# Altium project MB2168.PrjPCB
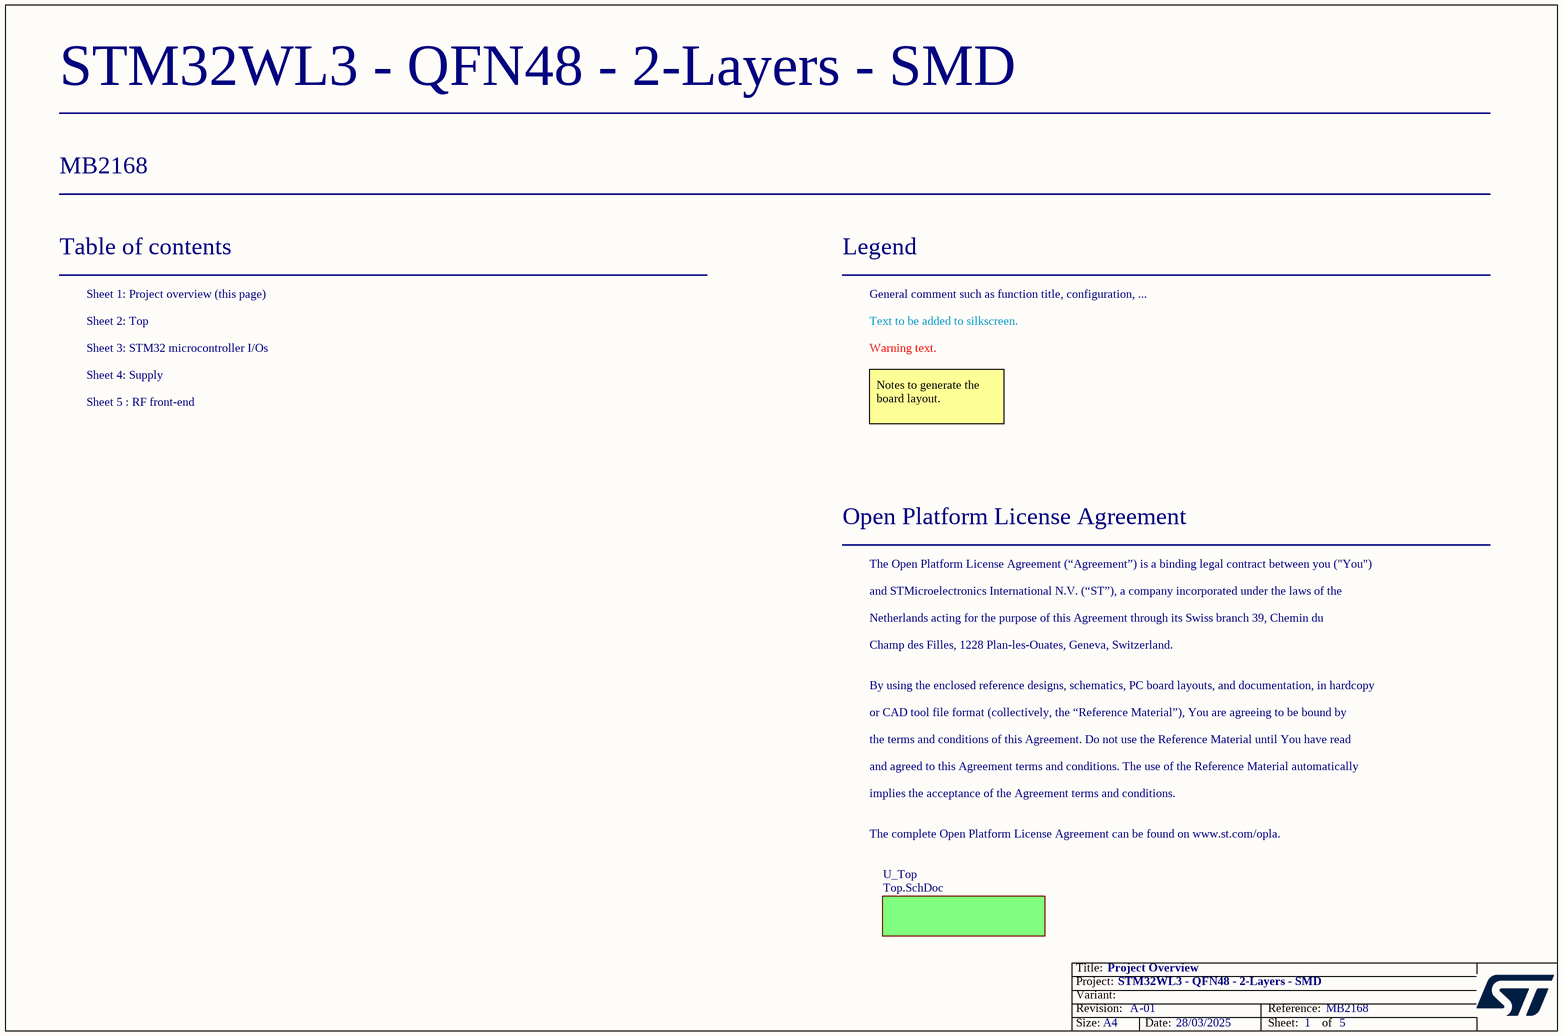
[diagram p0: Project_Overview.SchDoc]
Board_Reference: MB2168; Board_PCB_Revision: A; Board_Name: STM32WL3 - QFN48 - 2-Layers - SMD; Board_Document_Date: 28/03/2025; Board_Assembly_Revision: 01
5 sheets, 80 parts. Net scope: flat (ports and power ports of the same name join across sheets).
Board file: MB2168.PcbDoc
Sheets:
  Project_Overview.SchDoc
    U_Top = Top.SchDoc
      Designator = MCU_IOs.SchDoc
      Designator = RF.SchDoc
      Designator = Supply.SchDoc

## Sheet Project_Overview.SchDoc: Project Overview
size A4; Date: Not used; ApprovedBy: Not used; CheckedBy: Not used; Author: Not used; CompanyName: STMicroelectronics; DrawnBy: Not used; Engineer: Not used; Organization: Not used; Address1: Not used; Address2: Not used; Address3: Not used; Address4: Not used; DocumentNumber: Not used; Revision: Not used; SheetNumber: 1; SheetTotal: 5

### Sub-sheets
U_Top = Top.SchDoc: no entries

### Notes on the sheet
- Table of contents
- Sheet 1: Project overview (this page)
- Legend
- General comment such as function title, configuration, ...
- Sheet 2: Top
- Sheet 3: STM32 microcontroller I/Os
- Sheet 4: Supply
- Text to be added to silkscreen.
- Warning text.
- Sheet 5 : RF front-end
- Notes to generate the board layout.
- Open Platform License Agreement
- The Open Platform License Agreement (“Agreement”) is a binding legal contract between you ("You")
- and STMicroelectronics International N.V. (“ST”), a company incorporated under the laws of the
- Netherlands acting for the purpose of this Agreement through its Swiss branch 39, Chemin du
- Champ des Filles, 1228 Plan-les-Ouates, Geneva, Switzerland.
- By using the enclosed reference designs, schematics, PC board layouts, and documentation, in hardcopy
- or CAD tool file format (collectively, the “Reference Material”), You are agreeing to be bound by
- the terms and conditions of this Agreement. Do not use the Reference Material until You have read
- and agreed to this Agreement terms and conditions. The use of the Reference Material automatically
- implies the acceptance of the Agreement terms and conditions.
- The complete Open Platform License Agreement can be found on www.st.com/opla.

## Sheet Top.SchDoc: Top Schematic
size A4; Date: Not used; ApprovedBy: Not used; CheckedBy: Not used; Author: Not used; CompanyName: STMicroelectronics; DrawnBy: Not used; Engineer: Not used; Organization: Not used; Address1: Not used; Address2: Not used; Address3: Not used; Address4: Not used; DocumentNumber: Not used; Revision: Not used; SheetNumber: 2; SheetTotal: 4
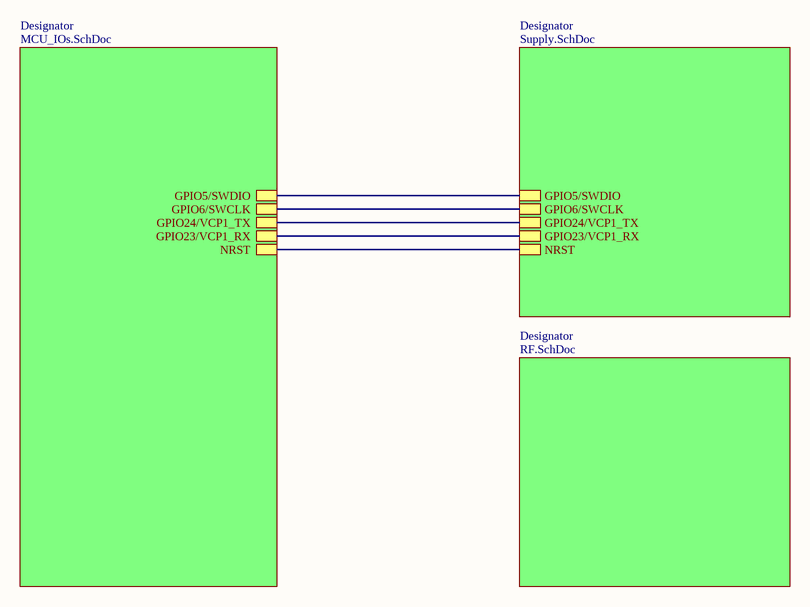
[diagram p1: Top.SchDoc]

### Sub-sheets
Designator = MCU_IOs.SchDoc: NRST, GPIO5/SWDIO, GPIO6/SWCLK, GPIO24/VCP1_TX, GPIO23/VCP1_RX
Designator = RF.SchDoc: no entries
Designator = Supply.SchDoc: NRST, GPIO5/SWDIO, GPIO6/SWCLK, GPIO23/VCP1_RX, GPIO24/VCP1_TX

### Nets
(unnamed): sheet Designator/NRST, sheet Designator/NRST
(unnamed): sheet Designator/GPIO5/SWDIO, sheet Designator/GPIO5/SWDIO  [a separate net that carries the same name]
(unnamed): sheet Designator/GPIO6/SWCLK, sheet Designator/GPIO6/SWCLK  [a separate net that carries the same name]
(unnamed): sheet Designator/GPIO24/VCP1_TX, sheet Designator/GPIO24/VCP1_TX  [a separate net that carries the same name]
(unnamed): sheet Designator/GPIO23/VCP1_RX, sheet Designator/GPIO23/VCP1_RX  [a separate net that carries the same name]

## Sheet MCU_IOs.SchDoc: STM32 I/Os & Clock
size A4; Date: Not used; ApprovedBy: Not used; CheckedBy: Not used; Author: Not used; CompanyName: STMicroelectronics; DrawnBy: Not used; Engineer: Not used; Organization: Not used; Address1: Not used; Address2: Not used; Address3: Not used; Address4: Not used; DocumentNumber: Not used; Revision: Not used; SheetNumber: 3; SheetTotal: 5
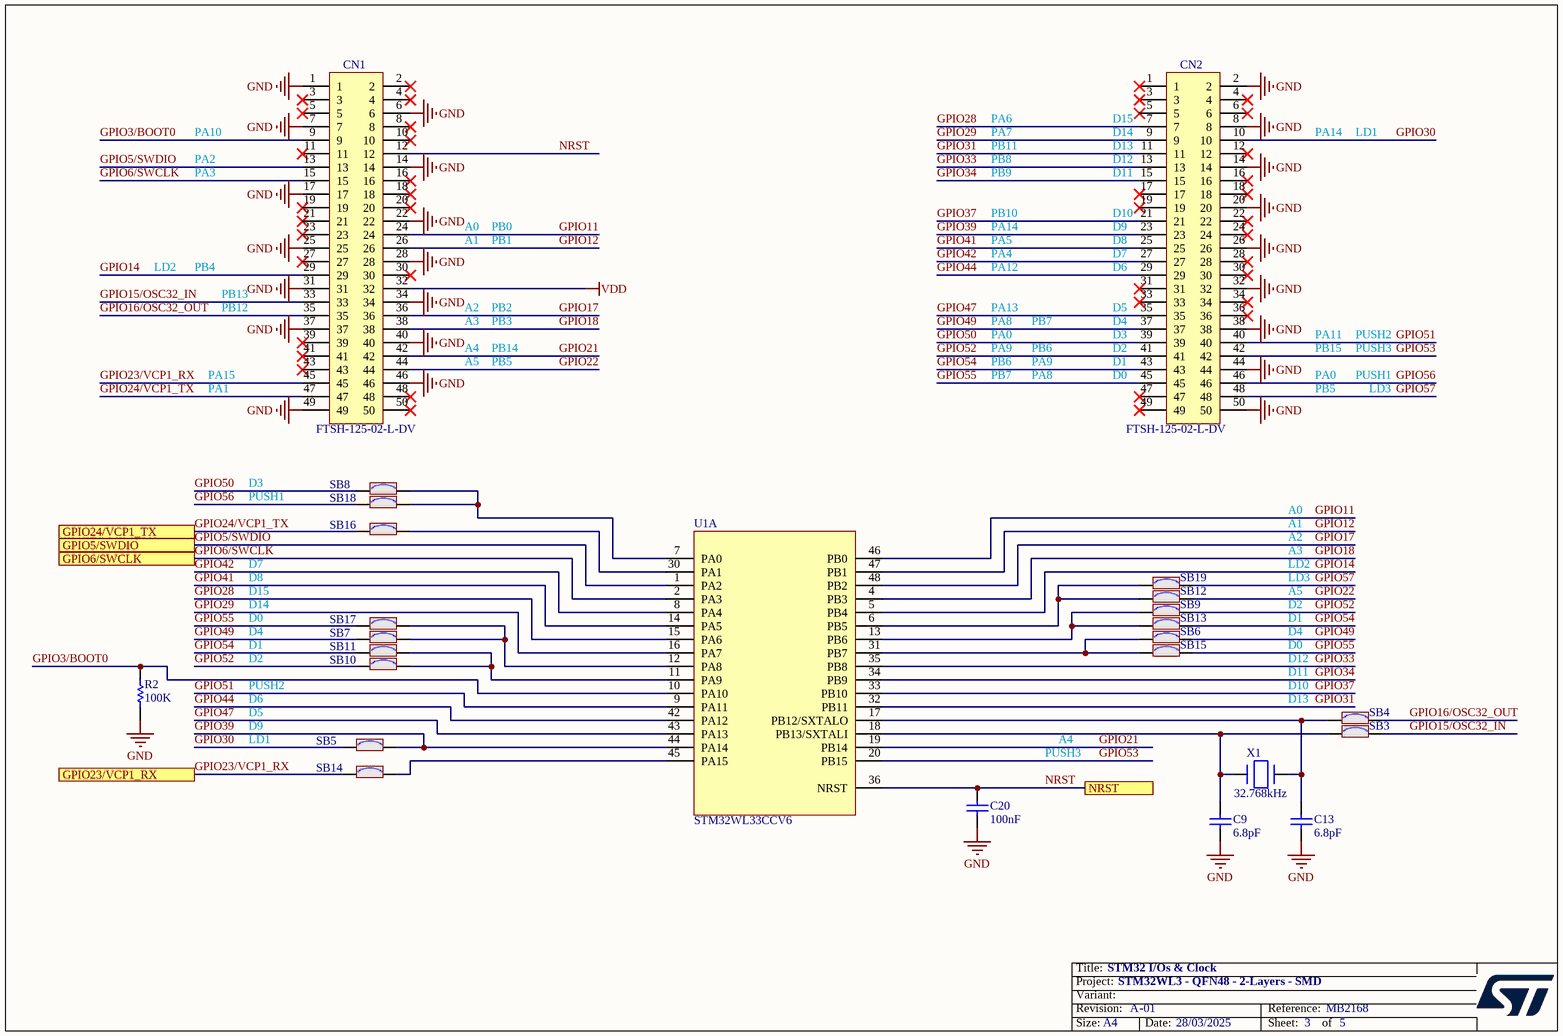
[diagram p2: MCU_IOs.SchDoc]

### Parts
C9  value 6.8pF  [GRM155--GJM155-0_05-MFG]  (hidden comment: Capacitor)
C13  value 6.8pF  [GRM155--GJM155-0_05-MFG]  (hidden comment: Capacitor)
C20  value 100nF  [GRM155--GJM155-0_05-MFG]  (hidden comment: Capacitor)
CN1  FTSH-125-02-L-DV  [CON_SAMTEC_FTSH-125-02-L-DV]
CN2  FTSH-125-02-L-DV  [CON_SAMTEC_FTSH-125-02-L-DV]
R2  value 100K  [R0402]  (hidden comment: Resistor)
SB3  SB_ON  [SOLDER-BRIDGE_R0402-0R]  (value not drawn)
SB4  SB_ON  [SOLDER-BRIDGE_R0402-0R]  (value not drawn)
SB5  SB_ON  [SOLDER-BRIDGE_R0402-0R]  (value not drawn)
SB6  SB_ON  [SOLDER-BRIDGE_R0402-0R]  (value not drawn)
SB7  SB_ON  [SOLDER-BRIDGE_R0402-0R]  (value not drawn)
SB8  SB_ON  [SOLDER-BRIDGE_R0402-0R]  (value not drawn)
SB9  SB_ON  [SOLDER-BRIDGE_R0402-0R]  (value not drawn)
SB10  SB_ON  [SOLDER-BRIDGE_R0402-0R]  (value not drawn)
SB11  SB_ON  [SOLDER-BRIDGE_R0402-0R]  (value not drawn)
SB12  SB_ON  [SOLDER-BRIDGE_R0402-0R]  (value not drawn)
SB13  SB_ON  [SOLDER-BRIDGE_R0402-0R]  (value not drawn)
SB14  SB_ON  [SOLDER-BRIDGE_R0402-0R]  (value not drawn)
SB15  SB_ON  [SOLDER-BRIDGE_R0402-0R]  (value not drawn)
SB16  SB_ON  [SOLDER-BRIDGE_R0402-0R]  (value not drawn)
SB17  SB_ON  [SOLDER-BRIDGE_R0402-0R]  (value not drawn)
SB18  SB_ON  [SOLDER-BRIDGE_R0402-0R]  (value not drawn)
SB19  SB_ON  [SOLDER-BRIDGE_R0402-0R]  (value not drawn)
U1  value STM32WL33CCV6  [ICC_QFN48-EPAD-4P5X4P5_6X6_P040]  (hidden comment: STM32WL33)  (part A of 3)
X1  value 32.768kHz  [CRY_NX2012SA_2P]  (hidden comment: XTAL_2_PINS)

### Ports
GPIO5/SWDIO, GPIO6/SWCLK, GPIO23/VCP1_RX, GPIO24/VCP1_TX, NRST

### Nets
GND: C9.1 C13.1 C20.1 CN1.1 CN1.6 CN1.7 CN1.14 CN1.17 CN1.22 CN1.25 CN1.28 CN1.31 CN1.34 CN1.37 CN1.40 CN1.46 CN1.49 CN2.2 CN2.8 CN2.14 CN2.20 CN2.26 CN2.32 CN2.38 CN2.44 CN2.50 R2.1
VDD: CN1.32
GPIO3/BOOT0: CN1.9 R2.2 U1.10(PA10)
GPIO5/SWDIO: CN1.13 U1.1(PA2) ; port GPIO5/SWDIO
GPIO6/SWCLK: CN1.15 U1.2(PA3) ; port GPIO6/SWCLK
GPIO11: CN1.24 U1.46(PB0)
GPIO12: CN1.26 U1.47(PB1)
GPIO14: CN1.29 U1.5(PB4)
GPIO15/OSC32_IN: CN1.33 SB3.2
GPIO16/OSC32_OUT: CN1.35 SB4.2
GPIO17: CN1.36 U1.48(PB2)
GPIO18: CN1.38 U1.4(PB3)
GPIO21: CN1.42 U1.19(PB14)
GPIO22: CN1.44 SB12.2
GPIO23/VCP1_RX: CN1.45 SB14.1 ; port GPIO23/VCP1_RX
GPIO24/VCP1_TX: CN1.47 SB16.1 ; port GPIO24/VCP1_TX
GPIO28: CN2.7 U1.15(PA6)
GPIO29: CN2.9 U1.16(PA7)
GPIO30: CN2.10 SB5.1
GPIO31: CN2.11 U1.32(PB11)
GPIO33: CN2.13 U1.35(PB8)
GPIO34: CN2.15 U1.34(PB9)
GPIO37: CN2.21 U1.33(PB10)
GPIO39: CN2.23 SB5.2 U1.44(PA14)
GPIO41: CN2.25 U1.14(PA5)
GPIO42: CN2.27 U1.8(PA4)
GPIO44: CN2.29 U1.42(PA12)
GPIO47: CN2.35 U1.43(PA13)
GPIO49: CN2.37 SB6.2 SB7.1
GPIO50: CN2.39 SB8.1
GPIO51: CN2.40 U1.9(PA11)
GPIO52: CN2.41 SB9.2 SB10.1
GPIO53: CN2.42 U1.20(PB15)
GPIO54: CN2.43 SB11.1 SB13.2
GPIO55: CN2.45 SB15.2 SB17.1
GPIO56: CN2.46 SB18.1
GPIO57: CN2.48 SB19.2
NRST: C20.2 CN1.12 U1.36(NRST) ; port NRST
NetC9_2: C9.2 SB3.1 U1.18(PB13/SXTALI) X1.2(X2)
NetC13_2: C13.2 SB4.1 U1.17(PB12/SXTALO) X1.1(X1)
NetSB6_1: SB6.1 SB15.1 U1.31(PB7)
NetSB7_2: SB7.2 SB17.2 U1.12(PA8)
NetSB8_2: SB8.2 SB18.2 U1.7(PA0)
NetSB9_1: SB9.1 SB13.1 U1.13(PB6)
NetSB10_2: SB10.2 SB11.2 U1.11(PA9)
NetSB12_1: SB12.1 SB19.1 U1.6(PB5)
NetSB14_2: SB14.2 U1.45(PA15)
NetSB16_2: SB16.2 U1.30(PA1)

Not connected (* = marked no-connect by the designer): CN1 2* 3* 4* 5* 8* 10* 11* 16* 18* 19* 20* 21* 23* 27* 30* 39* 41* 43* 48* 50*; CN2 1* 3* 4* 5* 6* 12* 16* 17* 18* 19* 22* 24* 28* 30* 31* 33* 34* 36* 47* 49*

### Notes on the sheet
- PA10
- PA2
- PA3
- PA7
- PA6
- PB8
- PB11
- PB9
- (near CN2) D11
- (near CN2) D13
- (near CN2) D14
- (near CN2) D15
- (near CN2) D12
- PA14
- LD1
- A0
- A1
- PB1
- PB0
- PA5
- PB10
- (near CN2) D10
- (near CN2) D9
- (near CN2) D8
- LD2
- PB4
- PB13
- PB12
- A2
- PB2
- PA13
- PA12
- PA4
- (near CN2) D7
- (near CN2) D6
- (near CN2) D5
- PA15
- A5
- A4
- A3
- PB5
- PB14
- PB3
- PB7
- PB6
- PA0
- PA9
- PA8
- (near CN2) D1
- (near CN2) D4
- (near CN2) D3
- (near CN2) D2
- (near CN2) D0
- PA11
- PB15
- PUSH1
- PUSH2
- PUSH3
- PA1
- LD3
- D3
- D8
- D7
- D14
- D15
- D4
- D1
- D0
- D2
- D6
- D5
- D10
- D12
- D11
- D13
- D9

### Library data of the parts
C9 C13 = MCD-03452: Capacitor, MLCC, 6.8pF, ±0.05pF, C0G, 50V, 0402, T=0.5mm; Part_Preference: Recommended; Manufacturer: MURATA; Manufacturer_Part_Number: GJM1555C1H6R8WB01; Order_Code_RS: NA; ShowFields: YES; ID: 5568
C20 = MCD-00006: Capacitor, MLCC, 100nF, 16V, X7R, +/-10%, 0402, T=0.5mm; Manufacturer_Part_Number: CC0402KRX7R7BB104; Manufacturer: YAGEO; Alternate_Manufacturer_Part_Number: GCM155R71C104KA55D; Alternate_Manufacturer: MURATA; Part_Preference: Recommended; Order_Code_RS: 616-9701
CN1 CN2 = MCD-02746: Header, 25x2, 12.7mm, VR, SMD, T=4.83mm; Part_Type: Connector; Part_Preference: Recommended; Manufacturer: SAMTEC; Value: Header 25x2; ShowFields: YES; ID: 4858; Component_Country_Of_Origin: China, Costa Rica, Malaysia, USA, Vietnam
R2 = MCD-03301: Resistor, 100K, 0402, +/-1%, 1/16W; Part_Preference: Alternate; Manufacturer: YAGEO; Manufacturer_Part_Number: RT0402FRE07100KL; Alternate_EMS: M; ShowFields: YES; ID: 5417
SB3-SB19 = MCD-01618: Solder Bridge 0402 ON; Part_Type: Misc; Part_Preference: Recommended; Manufacturer: YAGEO; Manufacturer_Part_Number: RC0402JR-070RL; Order_Code_RS: 618-5804; Component_Country_Of_Origin: China
U1 = MCD-03488: IC, Programmable Sub-1GHz wireless SoC; Part_Preference: Recommended; Manufacturer: STMICROELECTRONICS; Component_Country_Of_Origin: Unknown; ShowFields: YES; ID: 5604
X1 = MCD-01445: Crystal, 32.768kHz, 7pF, +/-20ppm, 80K, 2.05x1.2mm; BMS_Part_Number: 9157043; Part_Type: Crystal_Osc; Part_Preference: Recommended; Manufacturer: NDK; Manufacturer_Part_Number: NX2012SA-32.768KHZ-EXS00A-MU00389; Component_Country_Of_Origin: Unknown; ShowFields: YES; ID: 3545

## Sheet RF.SchDoc: STM32 RF
size A4; Date: Not used; ApprovedBy: Not used; CheckedBy: Not used; Author: Not used; CompanyName: STMicroelectronics; DrawnBy: Not used; Engineer: Not used; Organization: Not used; Address1: Not used; Address2: Not used; Address3: Not used; Address4: Not used; DocumentNumber: Not used; Revision: Not used; SheetNumber: 5; SheetTotal: 5
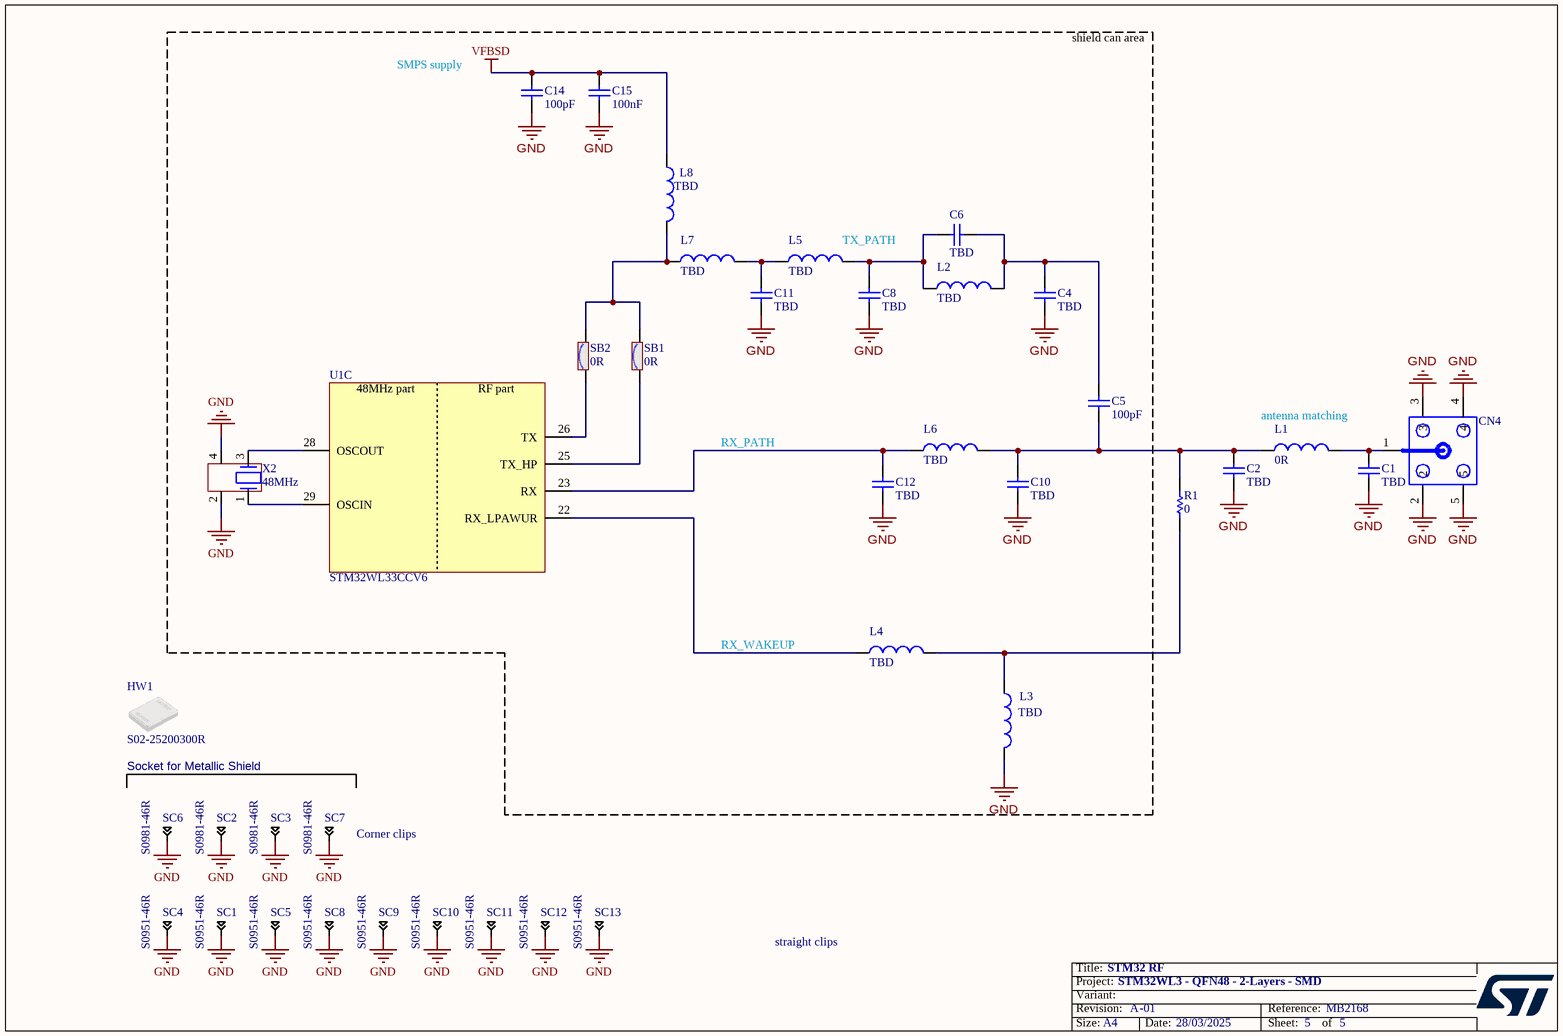
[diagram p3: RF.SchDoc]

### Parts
C1  value TBD  [GRM155--GJM155-0_05-MFG]  (hidden comment: Capacitor)
C2  value TBD  [GRM155--GJM155-0_05-MFG]  (hidden comment: Capacitor)
C4  value TBD  [GRM155--GJM155-0_05-MFG]  (hidden comment: Capacitor)
C5  value 100pF  [GRM155--GJM155-0_05-MFG]  (hidden comment: Capacitor)
C6  value TBD  [GRM155--GJM155-0_05-MFG]  (hidden comment: Capacitor)
C8  value TBD  [GRM155--GJM155-0_05-MFG]  (hidden comment: Capacitor)
C10  value TBD  [GRM155--GJM155-0_05-MFG]  (hidden comment: Capacitor)
C11  value TBD  [GRM155--GJM155-0_05-MFG]  (hidden comment: Capacitor)
C12  value TBD  [GRM155--GJM155-0_05-MFG]  (hidden comment: Capacitor)
C14  value 100pF  [GRM155--GJM155-0_05-MFG]  (hidden comment: Capacitor)
C15  value 100nF  [GRM155--GJM155-0_05-MFG]  (hidden comment: Capacitor)
CN4  mmcx  [CON_SMA-RF_CINCH_142-0701-851]  (value not drawn)
HW1  value S02-25200300R  [SHIELD_HARWIN_S02-25200300_15X20_H3]  (hidden comment: S02-20150300)
L1  value 0R  [L0402]  (hidden comment: Inductor)
L2  value TBD  [LQW15AN_00-W0_6-0_1-MFG]  (hidden comment: Inductor)
L3  value TBD  [L0402]  (hidden comment: Inductor)
L4  value TBD  [L0402]  (hidden comment: Inductor)
L5  value TBD  [LQW15AN_00-W0_6-0_1-MFG]  (hidden comment: Inductor)
L6  value TBD  [LQW15AN_00-W0_6-0_1-MFG]  (hidden comment: Inductor)
L7  value TBD  [LQW15AN_00-W0_6-0_1-MFG]  (hidden comment: Inductor)
L8  value TBD  [LQW15AN_00-W0_6-0_1-MFG]  (hidden comment: Inductor)
R1  value 0  [GRM155--GJM155-0_05-MFG]  (hidden comment: Resistor)
SB1  value 0R  [SOLDER-BRIDGE_R0201_0R]  (hidden comment: SB_ON)
SB2  value 0R  [SOLDER-BRIDGE_R0201_0R]  (hidden comment: SB_ON)
SC1  value S0951-46R  [CLIP_HARWIN_S0951-46R]  (hidden comment: Shield-clip_S0951-46R)
SC2  value S0981-46R  [CLIP_HARWIN_S0981-46R]  (hidden comment: Shield-clip_S0951-46R)
SC3  value S0981-46R  [CLIP_HARWIN_S0981-46R]  (hidden comment: Shield-clip_S0951-46R)
SC4  value S0951-46R  [CLIP_HARWIN_S0951-46R]  (hidden comment: Shield-clip_S0951-46R)
SC5  value S0951-46R  [CLIP_HARWIN_S0951-46R]  (hidden comment: Shield-clip_S0951-46R)
SC6  value S0981-46R  [CLIP_HARWIN_S0981-46R]  (hidden comment: Shield-clip_S0951-46R)
SC7  value S0981-46R  [CLIP_HARWIN_S0981-46R]  (hidden comment: Shield-clip_S0951-46R)
SC8  value S0951-46R  [CLIP_HARWIN_S0951-46R]  (hidden comment: Shield-clip_S0951-46R)
SC9  value S0951-46R  [CLIP_HARWIN_S0951-46R]  (hidden comment: Shield-clip_S0951-46R)
SC10  value S0951-46R  [CLIP_HARWIN_S0951-46R]  (hidden comment: Shield-clip_S0951-46R)
SC11  value S0951-46R  [CLIP_HARWIN_S0951-46R]  (hidden comment: Shield-clip_S0951-46R)
SC12  value S0951-46R  [CLIP_HARWIN_S0951-46R]  (hidden comment: Shield-clip_S0951-46R)
SC13  value S0951-46R  [CLIP_HARWIN_S0951-46R]  (hidden comment: Shield-clip_S0951-46R)
U1  value STM32WL33CCV6  [ICC_QFN48-EPAD-4P5X4P5_6X6_P040]  (hidden comment: STM32WL33)  (part C of 3)
X2  value 48MHz  [CRY_NX1612SA_4P]  (hidden comment: XTAL_4_PINS)

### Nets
GND: C1.1 C2.1 C4.1 C8.1 C10.1 C11.1 C12.1 C14.2 C15.1 CN4.2 CN4.3 CN4.4 CN4.5 L3.2 SC1.1 SC2.1 SC3.1 SC4.1 SC5.1 SC6.1 SC7.1 SC8.1 SC9.1 SC10.1 SC11.1 SC12.1 SC13.1 X2.2 X2.4
VFBSD: C14.1 C15.2 L8.1
NetC1_2: C1.2 CN4.1 L1.2
NetC2_2: C2.2 C5.1 C10.2 L1.1 L6.2 R1.2
NetC4_2: C4.2 C5.2 C6.2 L2.2
NetC6_1: C6.1 C8.2 L2.1 L5.2
NetC11_2: C11.2 L5.1 L7.2
NetC12_2: C12.2 L6.1 U1.23(RX)
NetL3_1: L3.1 L4.2 R1.1
NetL4_1: L4.1 U1.22(RX_LPAWUR)
NetL7_1: L7.1 L8.2 SB1.2 SB2.2
NetSB1_1: SB1.1 U1.25(TX_HP)
NetSB2_1: SB2.1 U1.26(TX)
NetU1_28: U1.28(OSCOUT) X2.3
NetU1_29: U1.29(OSCIN) X2.1

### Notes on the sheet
- shield can area
- SMPS supply
- (near L5) TX_PATH
- RX_PATH
- antenna matching
- RX_WAKEUP
- Socket for Metallic Shield
- (near SC7) Corner clips
- straight clips

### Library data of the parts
C1 = MCD-01600: Capacitor, MLCC, 0402, T=0.5mm; Part_Preference: Recommended; Manufacturer: YAGEO; Component_Country_Of_Origin: China; ShowFields: YES; ID: 3700
C2 = MCD-01600: Capacitor, MLCC, 0402, T=0.5mm; Part_Preference: Recommended; Component_Country_Of_Origin: China; ShowFields: YES; ID: 3700
C4 = MCD-03448: Capacitor, MLCC, 2.7pF, 50V, C0G, +/-0.05pF, C0G, 0402, T=0.5mm; Part_Preference: Recommended; Manufacturer: MURATA; ShowFields: YES; ID: 5564
C5 C14 = MCD-03446: Capacitor, MLCC, 100pF, 50V, COG, 1%, 0402, T=0.5mm; Part_Preference: Recommended; Manufacturer: MURATA; Manufacturer_Part_Number: GCM1555C1H101FA16; Order_Code_RS: 247-7780; ShowFields: YES; ID: 5562
C6 = MCD-02065: Capacitor, Monolithic CC, 1.2pF, 50V, +/-0.05pf, 0402, T=0.5mm; Part_Preference: Recommended; Manufacturer: MURATA; Order_Code_RS: 846-7246; Component_Country_Of_Origin: Japan; ShowFields: YES; ID: 4165
C8 = MCD-01374: Capacitor, MLCC, 5.6pF, 50V, NPO, +/-0.1pF, 0402, T=0.5mm; Part_Preference: Recommended; Manufacturer: YAGEO; Component_Country_Of_Origin: China; ShowFields: YES; ID: 3474
C10 = MCD-02994: Capacitor, MLCC, 1.5pF, 50V, C0G, +/-0.25pF, 0402, T=0.5mm; Part_Preference: Recommended; Manufacturer: MURATA; Component_Country_Of_Origin: Japan°; ShowFields: YES; ID: 5110
C11 = MCD-03555: Capacitor, MLCC, 5.3pF, 50V, C0G, +/-0.1pF, 0402, T=0.5mm; Part_Preference: Recommended; Manufacturer: MURATA; ShowFields: YES; ID: 5671
C12 = MCD-02215: Capacitor, MLCC, 0.5pF, 50V, C0G, +/-0.1pF, 0402, T=0.5mm; Part_Preference: Recommended; Manufacturer: MURATA; Order_Code_RS: 723-5111P; Component_Country_Of_Origin: Japan; ShowFields: YES; ID: 4315
C15 = MCD-03442: Capacitor, MLCC, 100nF, ±10%, X7R, 25V, 0402, T=0.5mm; Part_Preference: Recommended; Manufacturer: MURATA; Manufacturer_Part_Number: GRM155R71E104KE14D; Order_Code_RS: 247-8011; ShowFields: YES; ID: 5558
CN4 = MCD-02072: Jack_SMA, VR, PCB edge, 50R, T=7.92mm; Part_Type: Connector; Part_Preference: Recommended; Manufacturer: CINCH; Manufacturer_Part_Number: 142-0711-881; Order_Code_RS: 885-7532; Component_Country_Of_Origin: United States; ShowFields: YES; ID: 4172
HW1 = MCD-03503: RFI shield CAN, 25x20x3mm; Part_Type: Misc; Part_Preference: Recommended; Manufacturer: HARWIN; Order_Code_RS: 247-9196; Component_Country_Of_Origin: UK°; ShowFields: YES; ID: 5619
L1 = MCD-01937: Resistor, 0R, 0402, +/-5%, 1/16W; Part_Preference: Recommended; Manufacturer: YAGEO; Manufacturer_Part_Number: RC0402JR-070RL; Order_Code_RS: 618-5804; Component_Country_Of_Origin: China; ShowFields: YES; ID: 4037
L2 = MCD-03460: Inductor, Wire-wound, 5.6nH, ±0.1nH, 1770mA, 40mR, 0402, T=0.5mm; Part_Preference: Recommended; Manufacturer: MURATA; Order_Code_RS: NA; ShowFields: YES; ID: 5576
L3 = MCD-03462: Inductor, MLCC, 5.6nH, ±0.3nH, 650mA, 180mR, 0402, T=0.5mm; Part_Preference: Recommended; Manufacturer: MURATA; Order_Code_RS: 124-8165; ShowFields: YES; ID: 5578
L4 = MCD-03461: Inductor, 6.8nH, +/-3%, 0.6A, 220mR, 0402, T=0.5mm; Manufacturer: MURATA
L5 = MCD-03459: Inductor, Wire-wound, 6.2nH, ±0.1nH, 1600mA, 56mR, 0402, T=0.5mm; Part_Preference: Recommended; Manufacturer: MURATA; Order_Code_RS: NA; ShowFields: YES; ID: 5575
L6 = MCD-01766: Inductor, 15nH, +/-2%, Itemp=460mA max, 0R16, 0402, T= 0.6mm, Qmin=30; Manufacturer: MURATA
L7 = MCD-03457: Inductor, Wire-wound, 3.6nH, ±0.1nH, 1950mA, 30mR, 0402, T=0.5mm; Part_Preference: Recommended; Manufacturer: MURATA; Order_Code_RS: 166-9582; ShowFields: YES; ID: 5573
L8 = MCD-03456: Inductor, Wire-wound, 12nHH, ±2%, 500mA, 1405mR, 0402, T=0.5mm; Part_Preference: Recommended; Manufacturer: MURATA; Order_Code_RS: 167-4829; ShowFields: YES; ID: 5572
R1 = MCD-03301: 0 ohm resistor; Part_Preference: Alternate; Manufacturer: YAGEO; Manufacturer_Part_Number: RC0402JR-070RL; Alternate_EMS: M; ShowFields: YES; ID: 5417
SB1 SB2 = MCD-03219: Resistor, 0R, 0201, Solder Bridge ON , 1/20W,; Part_Type: Misc; Part_Preference: Recommended; Manufacturer: YAGEO; Manufacturer_Part_Number: RC0201JR-070RL; Order_Code_RS: 198-7623; Component_Country_Of_Origin: China; ShowFields: YES; ID: 5335
SC1 SC4 SC5 SC8 = MCD-01587: shield clip Harwin S0951-46R to fix RF shielded cavity; Part_Type: Misc; Part_Preference: Recommended; Component_Country_Of_Origin: South Korea
SC2 SC3 SC6 SC7 = MCD-02164: shield clip Harwin S0981-46R to fix RF shielded cavity - SMT RFI Shield Clip, Corner (T+R); Part_Type: Misc; Part_Preference: Recommended; Order_Code_RS: 161-3702; Component_Country_Of_Origin: South Korea; ShowFields: YES; ID: 4264
SC9-SC13 = MCD-01587: RFI shield clip mini TIN SMD; Part_Type: Mechanical; Part_Preference: Recommended; Manufacturer: HARWIN; Component_Country_Of_Origin: South Korea; ShowFields: YES; ID: 3687
U1 = MCD-03488: as U1 on sheet MCU_IOs
X2 = MCD-03559: Crystal, 48MHz, 8pF, +/-10 ppm, 22R, 1.6x1.2mm; Part_Type: Crystal_Osc; Part_Preference: Recommended; Manufacturer: NDK; Manufacturer_Part_Number: NX1612SA-48.000 MHz-EXS00A-CS12140; ShowFields: YES; ID: 5675

## Sheet Supply.SchDoc: STM32 power
size A4; Date: Not used; ApprovedBy: Not used; CheckedBy: Not used; Author: Not used; CompanyName: STMicroelectronics; DrawnBy: Not used; Engineer: Not used; Organization: Not used; Address1: Not used; Address2: Not used; Address3: Not used; Address4: Not used; DocumentNumber: Not used; Revision: Not used; SheetNumber: 4; SheetTotal: 5
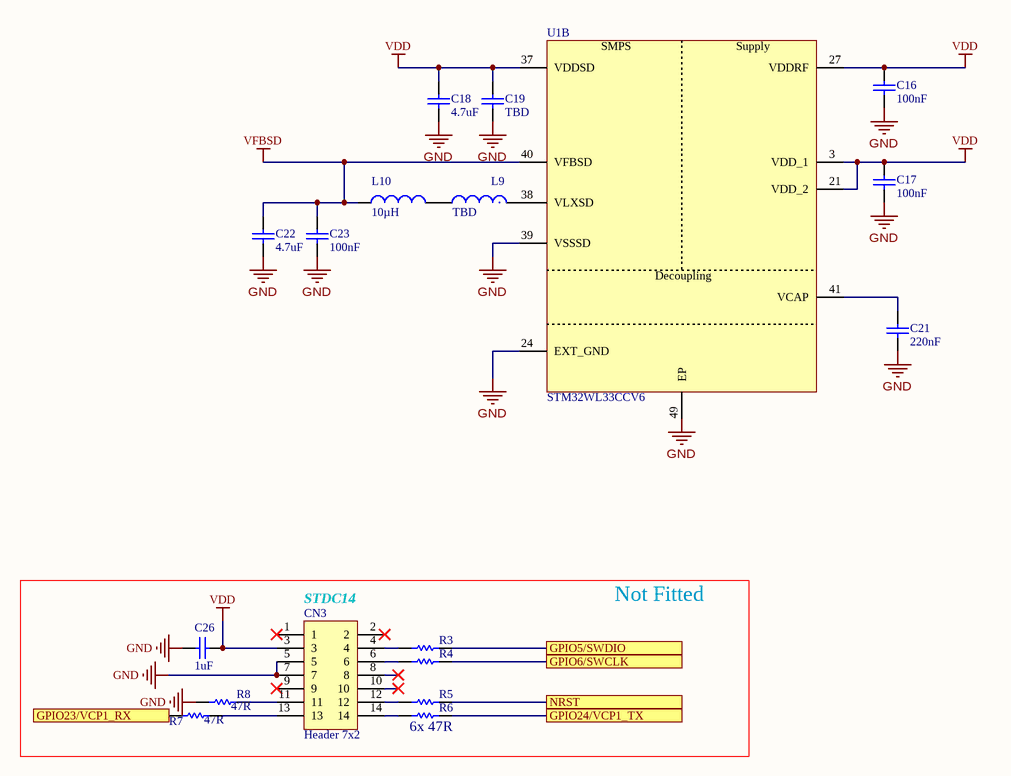
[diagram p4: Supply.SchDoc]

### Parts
C16  value 100nF  [GRM155--GJM155-0_05-MFG]  (hidden comment: Capacitor)
C17  value 100nF  [GRM155--GJM155-0_05-MFG]  (hidden comment: Capacitor)
C18  value 4.7uF  [GRM155--GJM155-0_05-MFG]  (hidden comment: Capacitor)
C19  value TBD  [GRM155--GJM155-0_05-MFG]  (hidden comment: Capacitor)
C21  value 220nF  [GRM155--GJM155-0_05-MFG]  (hidden comment: Capacitor)
C22  value 4.7uF  [GRM155--GJM155-0_05-MFG]  (hidden comment: Capacitor)
C23  value 100nF  [GRM155--GJM155-0_05-MFG]  (hidden comment: Capacitor)
C26  value 1uF  [C0603]  (hidden comment: Capacitor)
CN3  Header 7x2  [CON_SAMTEC_FTSH-107-01-L-DV-K-A]
L9  value TBD  [LQG15HH_02-IPC_C]  (hidden comment: Inductor)
L10  value 10µH  [LQM21FN_70-IPC_C]  (hidden comment: Inductor)
R3  Resistor  [R0402]  (value not drawn)
R4  Resistor  [R0402]  (value not drawn)
R5  Resistor  [R0402]  (value not drawn)
R6  Resistor  [R0402]  (value not drawn)
R7  value 47R  [R0402]  (hidden comment: Resistor)
R8  value 47R  [R0402]  (hidden comment: Resistor)
U1  value STM32WL33CCV6  [ICC_QFN48-EPAD-4P5X4P5_6X6_P040]  (hidden comment: STM32WL33)  (part B of 3)

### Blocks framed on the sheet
Not Fitted: C26 CN3 R3-R8

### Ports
GPIO5/SWDIO, GPIO6/SWCLK, GPIO23/VCP1_RX, GPIO24/VCP1_TX, NRST

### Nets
GND: C16.1 C17.1 C18.1 C19.1 C21.1 C22.1 C23.2 C26.1 CN3.5 CN3.7 R8.1 U1.24(EXT_GND) U1.39(VSSSD) U1.49(EP)
VDD: C16.2 C17.2 C18.2 C19.2 C26.2 CN3.3 U1.3(VDD_1) U1.21(VDD_2) U1.27(VDDRF) U1.37(VDDSD)
VFBSD: C22.2 C23.1 L10.1 U1.40(VFBSD)
GPIO5/SWDIO: R3.2 ; port GPIO5/SWDIO
GPIO6/SWCLK: R4.2 ; port GPIO6/SWCLK
GPIO23/VCP1_RX: R7.1 ; port GPIO23/VCP1_RX
GPIO24/VCP1_TX: R6.2 ; port GPIO24/VCP1_TX
NRST: R5.2 ; port NRST
NetC21_2: C21.2 U1.41(VCAP)
NetCN3_4: CN3.4 R3.1
NetCN3_6: CN3.6 R4.1
NetCN3_11: CN3.11 R8.2
NetCN3_12: CN3.12 R5.1
NetCN3_13: CN3.13 R7.2
NetCN3_14: CN3.14 R6.1
NetL9_1: L9.1 U1.38(VLXSD)
NetL9_2: L9.2 L10.2

Not connected (* = marked no-connect by the designer): CN3 1* 2* 8* 9* 10*

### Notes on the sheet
- (near CN3) STDC14
- (near R6) 6x 47R

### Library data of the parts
C16 C17 = MCD-03442: Capacitor, MLCC, 100nF, +/-10%, X7R, 25V, 0402, T=0.5mm; Part_Preference: Recommended; Manufacturer: MURATA; Manufacturer_Part_Number: GRM155R71E104KE14D; Order_Code_RS: 247-8011; ShowFields: YES; ID: 5558; Component_Country_Of_Origin: Japan°
C18 C22 = MCD-03431: Capacitor, MLCC, 4.7uF, X5R, 10 V, 0402, ± 20%, T=0.5mm; Part_Preference: Recommended; Manufacturer: MURATA; Manufacturer_Part_Number: GRM155R61A475MEAAD; Order_Code_RS: 172-6870; ShowFields: YES; ID: 5547
C19 = MCD-03442: Capacitor, MLCC, 100nF, ±10%, X7R, 25V, 0402, T=0.5mm; Part_Preference: Recommended; Manufacturer: MURATA; Order_Code_RS: 247-8011; ShowFields: YES; ID: 5558
C21 = MCD-03077: Capacitor, MLCC, 220nF, 35V, X6S, +/-10%, 0402, T=0.5mm; Part_Preference: Recommended; Manufacturer: MURATA; Manufacturer_Part_Number: GRM155C8YA224KE01D; Component_Country_Of_Origin: Japan°; ShowFields: YES; ID: 5193
C23 = MCD-03442: as C15 on sheet RF
C26 = MCD-00010: Capacitor, MLCC, 1uF, 16V, X5R, 10%, 0603, T=0,8mm; Manufacturer_Part_Number: CC0603KRX5R7BB105; Manufacturer: YAGEO; Provided_By: Subcon; Initial_Board_Reference: MB1274
CN3 = MCD-01531: Header, 7x2, 1.27mm, VR, T=5.97mm, FTSH series STDC14 without Alignment Pin; Part_Type: Connector; Part_Preference: Recommended; Manufacturer: SAMTEC; Manufacturer_Part_Number: FTSH-107-01-L-DV-K; Order_Code_RS: 179-9021; Component_Country_Of_Origin: China, Costa Rica, Malaysia, United States, Vietnam
L9 = MCD-03453: Inductor, MLCC, 100nH, ±5%, 200mA, 1.25R, 0402, T=0.5mm; Part_Preference: Recommended; Manufacturer: MURATA; Manufacturer_Part_Number: LQG15HSR10J02; Order_Code_RS: 166-9735; ShowFields: YES; ID: 5569
L10 = MCD-03557: Inductor, 10uH, +/-20%, 100mA, 1R36, 0805, T=0.8mm; Part_Preference: Recommended; Manufacturer: MURATA; Manufacturer_Part_Number: LQM21FN100M80; ShowFields: YES; ID: 5673
R3-R8 = MCD-00481: Resistor,47R,0402,1%,1/16W; Manufacturer_Part_Number: RC0402FR-0747RL; Manufacturer: YAGEO; Provided_By: Subcon
U1 = MCD-03488: as U1 on sheet MCU_IOs

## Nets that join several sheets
GND: MCU_IOs (27 pins), RF (29 pins), Supply (14 pins)
VDD: MCU_IOs (CN1.32), Supply (10 pins)
VFBSD: RF (C14.1 C15.2 L8.1), Supply (C22.2 C23.1 L10.1 U1.40)
GPIO5/SWDIO: MCU_IOs (CN1.13 U1.1), Supply (R3.2)
GPIO6/SWCLK: MCU_IOs (CN1.15 U1.2), Supply (R4.2)
GPIO23/VCP1_RX: MCU_IOs (CN1.45 SB14.1), Supply (R7.1)
GPIO24/VCP1_TX: MCU_IOs (CN1.47 SB16.1), Supply (R6.2)
NRST: MCU_IOs (C20.2 CN1.12 U1.36), Supply (R5.2)

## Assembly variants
868_16dBm: not fitted C1 C2 C10 C12 C16 C26 CN3 HW1 L3 R1 R3 R4 R5 R6 R7 R8 SB2 SB3 SB4 SB6 SB9 SB11 SB17
433_16dBm: not fitted C1 C2 C6 C10 C12 C26 CN3 HW1 L3 R1 R3 R4 R5 R6 R7 R8 SB2 SB3 SB4 SB6 SB9 SB11 SB17
433_10dBm: not fitted C1 C2 C6 C10 C12 C26 CN3 HW1 L3 R1 R3 R4 R5 R6 R7 R8 SB1 SB3 SB4 SB6 SB9 SB11 SB17
915_10dBm: not fitted C1 C2 C6 C10 C12 C26 CN3 L3 R1 R3 R4 R5 R6 R7 R8 SB1 SB3 SB4 SB6 SB9 SB11 SB17
868_10dBm: not fitted C1 C2 C6 C10 C12 C26 CN3 HW1 L3 R1 R3 R4 R5 R6 R7 R8 SB1 SB3 SB4 SB6 SB9 SB11 SB17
